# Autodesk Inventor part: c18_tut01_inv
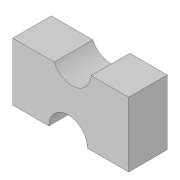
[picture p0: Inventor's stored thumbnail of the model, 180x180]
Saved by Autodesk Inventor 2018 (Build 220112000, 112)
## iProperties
Created: 2017-06
Part Number: c18_tut01_inv
Material: Generic
Document SubType Name: Modeling
Designer: CADCIM 00
Density: 1 g/cm^3
Appearance: Default
Author: CADCIM 00
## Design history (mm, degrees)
sketch "Sketch1"
  geometry: L1 (-60, 0)-(-60, 33.532); L2 (0, 30)-(0, 0); L3 (-60, 33.532)-(-40.6, 33.532); L4 (-21.474, 30)-(0, 30); L5 (0, 0)-(-18.704, 0); L6 (-38.704, 0)-(-60, 0); A1 r 10 centre (-30.614, 34.057) between (-40.6, 33.532) and (-21.474, 30); A2 r 10 centre (-28.704, 0) between (-18.704, 0) and (-38.704, 0)
  constraints: 12 end point, 5 parallel, 4 point on circle, 2 centre point, 2 horizontal, 2 perpendicular, 1 equal radius
  dimensions: "d0" = 60 distance between parallel lines of L1 L2 (= LEN); "d1" = 30 distance of L2.start L2.end (= WID); "d2" = 10 radius of A2 (= RAD)
extrude "Extrusion1" new body sketch "Sketch1" distance "d3" = 20 (= EXT); taper "d4" = 0 deg
body "Solid1"
other parameters: "LEN" = 60 [user parameter; used in 4 equation terms], "WID" = 30 (= 0.5 x LEN) [user parameter; used in 1 equation term], "RAD" = 10 (= 0.166667 x LEN) [user parameter; used in 1 equation term], "EXT" = 20 (= 0.333333 x LEN) [user parameter; used in 1 equation term]
